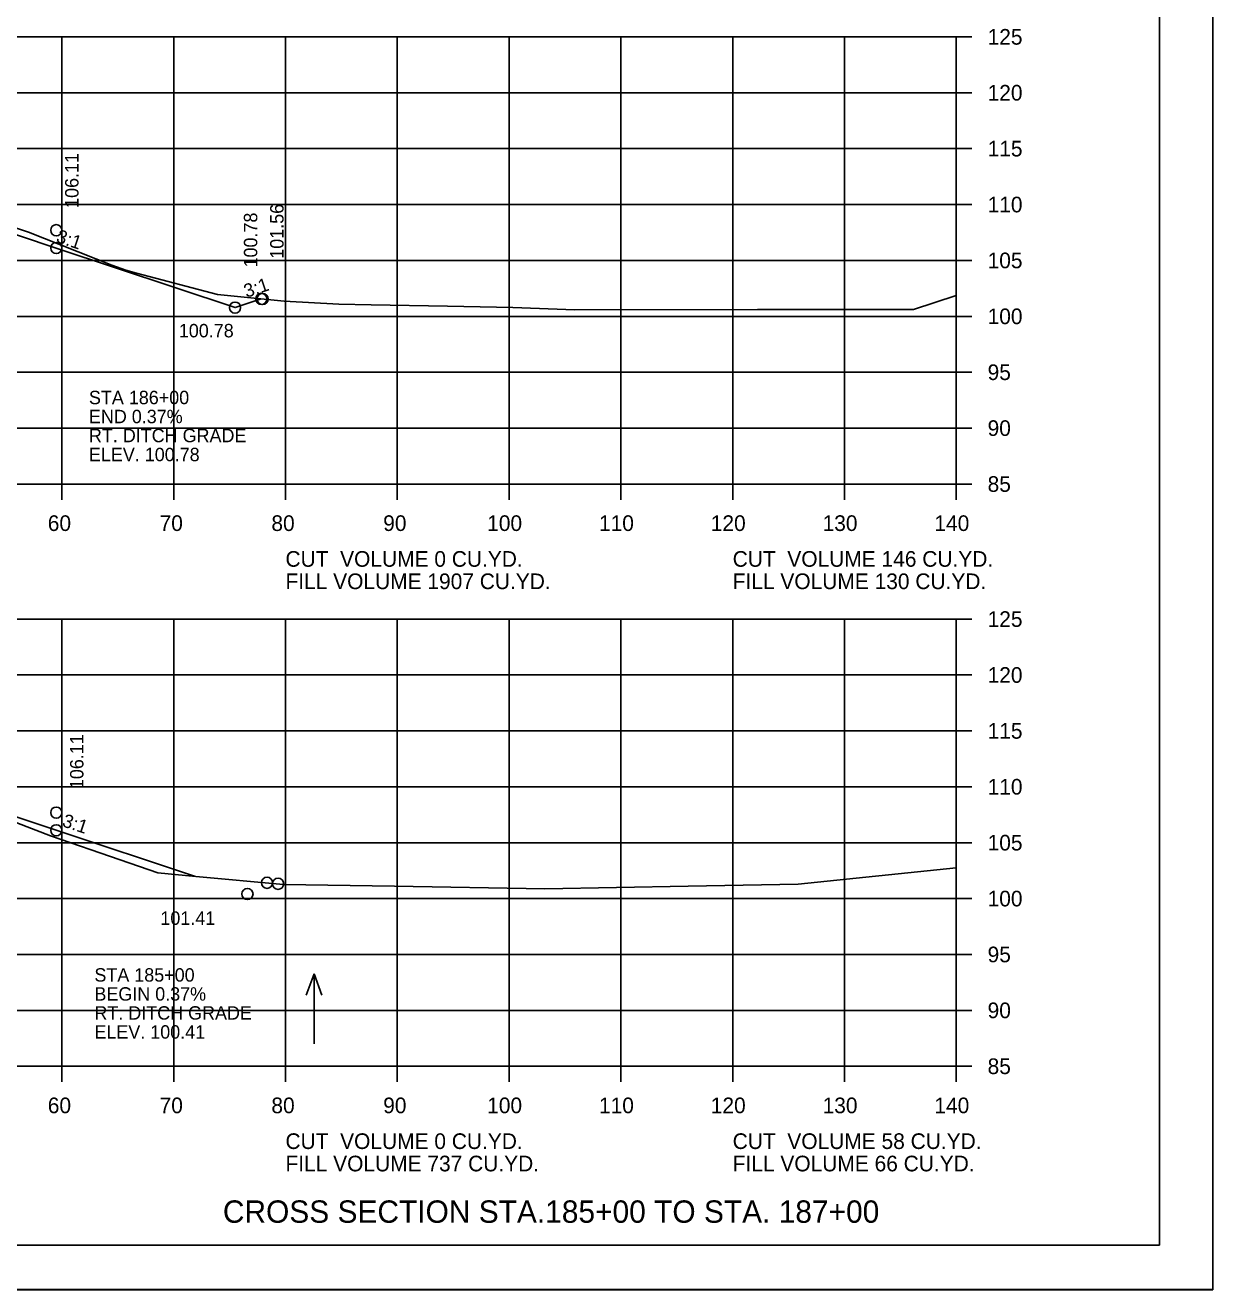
# Model space of a CAD drawing. Extents: x 1175611 to 1176402, y -433344 to -416213.
# Drawn here: x 1175837.7 to 1175943.9, y -426516.7 to -426403.6 of the extents above; entities that cross this region are included whole.
import ezdxf

# ---------------------------------------------------------------- set-up
doc = ezdxf.new("R2010")
doc.units = 0
for name, color, linetype in [('Default', 7, 'Continuous'), ('R_Axis', 7, 'Continuous'), ('R_Axis Annot', 7, 'Continuous'), ('R_Border', 7, 'Continuous'), ('R_Draft', 7, 'Continuous'), ('R_Exist Surface', 7, 'Continuous'), ('R_Fin Surface', 7, 'Continuous'), ('R_Grid', 7, 'Continuous'), ('R_No Plot', 7, 'Continuous'), ('R_Water Annot', 7, 'Continuous'), ('R_Xsect Elev', 7, 'Continuous'), ('R_Xsect Slope', 7, 'Continuous')]:
    doc.layers.add(name, color=color, linetype=linetype)

msp = doc.modelspace()

# ---------------------------------------------------------------- linework, layer by layer
at = {"layer": 'R_Axis'}
for p, q in [((1175920.97, -426444.65), (1175920.97, -426404.65)), ((1175922.37, -426404.65), (1175920.97, -426404.65)), ((1175922.37, -426409.65), (1175920.97, -426409.65)), ((1175922.37, -426414.65), (1175920.97, -426414.65)), ((1175922.37, -426419.65), (1175920.97, -426419.65)), ((1175922.37, -426424.65), (1175920.97, -426424.65)), ((1175922.37, -426429.65), (1175920.97, -426429.65)), ((1175922.37, -426434.65), (1175920.97, -426434.65)), ((1175922.37, -426439.65), (1175920.97, -426439.65)), ((1175640.97, -426444.65), (1175920.97, -426444.65)), ((1175840.97, -426446.05), (1175840.97, -426444.65)), ((1175850.97, -426446.05), (1175850.97, -426444.65)), ((1175860.97, -426446.05), (1175860.97, -426444.65)), ((1175870.97, -426446.05), (1175870.97, -426444.65)), ((1175880.97, -426446.05), (1175880.97, -426444.65)), ((1175890.97, -426446.05), (1175890.97, -426444.65)), ((1175900.97, -426446.05), (1175900.97, -426444.65)), ((1175910.97, -426446.05), (1175910.97, -426444.65)), ((1175920.97, -426446.05), (1175920.97, -426444.65)), ((1175922.37, -426444.65), (1175920.97, -426444.65)), ((1175920.97, -426496.73), (1175920.97, -426456.73)), ((1175922.37, -426456.73), (1175920.97, -426456.73)), ((1175922.37, -426461.73), (1175920.97, -426461.73)), ((1175922.37, -426466.73), (1175920.97, -426466.73)), ((1175922.37, -426471.73), (1175920.97, -426471.73)), ((1175922.37, -426476.73), (1175920.97, -426476.73)), ((1175922.37, -426481.73), (1175920.97, -426481.73)), ((1175922.37, -426486.73), (1175920.97, -426486.73)), ((1175922.37, -426491.73), (1175920.97, -426491.73)), ((1175640.97, -426496.73), (1175920.97, -426496.73)), ((1175840.97, -426498.13), (1175840.97, -426496.73)), ((1175850.97, -426498.13), (1175850.97, -426496.73)), ((1175860.97, -426498.13), (1175860.97, -426496.73)), ((1175870.97, -426498.13), (1175870.97, -426496.73)), ((1175880.97, -426498.13), (1175880.97, -426496.73)), ((1175890.97, -426498.13), (1175890.97, -426496.73)), ((1175900.97, -426498.13), (1175900.97, -426496.73)), ((1175910.97, -426498.13), (1175910.97, -426496.73)), ((1175920.97, -426498.13), (1175920.97, -426496.73)), ((1175922.37, -426496.73), (1175920.97, -426496.73))]:
    msp.add_line(p, q, dxfattribs=at)
at = {"layer": 'R_Border'}
for q in [(1175939.15, -426307.27), (1175622.97, -426512.73)]:
    msp.add_line((1175939.15, -426512.73), q, dxfattribs=at)
at = {"layer": 'R_Exist Surface'}
for points in [[(1175833.72, -426420.68), (1175837.99, -426422.12), (1175845.43, -426425.07), (1175846.69, -426425.52), (1175847.63, -426425.78), (1175854.88, -426427.71), (1175860.86, -426428.28), (1175865.73, -426428.57), (1175868.62, -426428.63), (1175875.45, -426428.73), (1175881.31, -426428.87), (1175886.84, -426429.07), (1175903.2, -426429.04), (1175917.14, -426429.03), (1175920.97, -426427.8)], [(1175833.52, -426473.65), (1175839.95, -426476.12), (1175846.17, -426478.28), (1175849.56, -426479.44), (1175852.94, -426479.75), (1175860.8, -426480.46), (1175870.71, -426480.63), (1175884.17, -426480.87), (1175896.99, -426480.62), (1175906.82, -426480.43), (1175920.97, -426478.97)]]:
    msp.add_lwpolyline(points, dxfattribs=at)
at = {"layer": 'R_Fin Surface'}
for points in [[(1175704.22, -426429.29), (1175721.47, -426423.54), (1175734.45, -426419.21), (1175737.97, -426418.04), (1175749.47, -426417.58), (1175751.47, -426417.54), (1175780.97, -426416.95), (1175810.47, -426417.54), (1175812.47, -426417.58), (1175823.97, -426418.04), (1175827.49, -426419.21), (1175840.47, -426423.54), (1175856.46, -426428.87), (1175858.81, -426428.09)], [(1175705.54, -426480.93), (1175721.47, -426475.62), (1175734.45, -426471.3), (1175737.97, -426470.12), (1175749.47, -426469.66), (1175751.47, -426469.62), (1175780.97, -426469.03), (1175810.47, -426469.62), (1175812.47, -426469.66), (1175823.97, -426470.12), (1175827.49, -426471.3), (1175840.47, -426475.62), (1175852.83, -426479.74)]]:
    msp.add_lwpolyline(points, dxfattribs=at)
at = {"layer": 'R_Grid'}
for p, q in [((1175640.97, -426404.65), (1175920.97, -426404.65)), ((1175840.97, -426444.65), (1175840.97, -426404.65)), ((1175850.97, -426444.65), (1175850.97, -426404.65)), ((1175860.97, -426444.65), (1175860.97, -426404.65)), ((1175870.97, -426444.65), (1175870.97, -426404.65)), ((1175880.97, -426444.65), (1175880.97, -426404.65)), ((1175890.97, -426444.65), (1175890.97, -426404.65)), ((1175900.97, -426444.65), (1175900.97, -426404.65)), ((1175910.97, -426444.65), (1175910.97, -426404.65)), ((1175920.97, -426444.65), (1175920.97, -426404.65)), ((1175640.97, -426409.65), (1175920.97, -426409.65)), ((1175640.97, -426414.65), (1175920.97, -426414.65)), ((1175640.97, -426419.65), (1175920.97, -426419.65)), ((1175640.97, -426424.65), (1175920.97, -426424.65)), ((1175640.97, -426429.65), (1175920.97, -426429.65)), ((1175640.97, -426434.65), (1175920.97, -426434.65)), ((1175640.97, -426439.65), (1175920.97, -426439.65)), ((1175640.97, -426444.65), (1175920.97, -426444.65)), ((1175640.97, -426456.73), (1175920.97, -426456.73)), ((1175840.97, -426496.73), (1175840.97, -426456.73)), ((1175850.97, -426496.73), (1175850.97, -426456.73)), ((1175860.97, -426496.73), (1175860.97, -426456.73)), ((1175870.97, -426496.73), (1175870.97, -426456.73)), ((1175880.97, -426496.73), (1175880.97, -426456.73)), ((1175890.97, -426496.73), (1175890.97, -426456.73)), ((1175900.97, -426496.73), (1175900.97, -426456.73)), ((1175910.97, -426496.73), (1175910.97, -426456.73)), ((1175920.97, -426496.73), (1175920.97, -426456.73)), ((1175640.97, -426461.73), (1175920.97, -426461.73)), ((1175640.97, -426466.73), (1175920.97, -426466.73)), ((1175640.97, -426471.73), (1175920.97, -426471.73)), ((1175640.97, -426476.73), (1175920.97, -426476.73)), ((1175640.97, -426481.73), (1175920.97, -426481.73)), ((1175640.97, -426486.73), (1175920.97, -426486.73)), ((1175640.97, -426491.73), (1175920.97, -426491.73)), ((1175640.97, -426496.73), (1175920.97, -426496.73))]:
    msp.add_line(p, q, dxfattribs=at)
at = {"layer": 'R_No Plot'}
msp.add_line((1175610.57, -426516.71), (1175943.91, -426516.71), dxfattribs=at)
msp.add_lwpolyline([(1175610.57, -426303.38), (1175943.91, -426303.38), (1175943.91, -426516.72), (1175610.57, -426516.72)], close=True, dxfattribs=at)
for centre in [(1175840.47, -426421.95), (1175840.47, -426423.54), (1175858.81, -426428.09), (1175858.81, -426428.09), (1175858.92, -426428.1), (1175858.92, -426428.1), (1175856.46, -426428.87), (1175856.46, -426428.87), (1175840.47, -426474.04), (1175840.47, -426475.62), (1175857.57, -426481.32), (1175857.57, -426481.32), (1175859.32, -426480.32), (1175860.31, -426480.41), (1175860.31, -426480.41)]:
    msp.add_circle(centre, 0.5, dxfattribs=at)
at = {"layer": 'R_Water Annot'}
for p, q in [((1175863.53, -426488.45), (1175862.83, -426490.37)), ((1175863.53, -426494.73), (1175863.53, -426488.45)), ((1175863.53, -426488.45), (1175864.23, -426490.37))]:
    msp.add_line(p, q, dxfattribs=at)

# ---------------------------------------------------------------- texts
at = {"layer": 'Default'}
for s, p in [('CUT  VOLUME 0 CU.YD.', (1175860.97, -426452.05)), ('CUT  VOLUME 146 CU.YD.', (1175900.97, -426452.05)), ('FILL VOLUME 1907 CU.YD.', (1175860.97, -426454.05)), ('FILL VOLUME 130 CU.YD.', (1175900.97, -426454.05)), ('CUT  VOLUME 0 CU.YD.', (1175860.97, -426504.13)), ('CUT  VOLUME 58 CU.YD.', (1175900.97, -426504.13)), ('FILL VOLUME 737 CU.YD.', (1175860.97, -426506.13)), ('FILL VOLUME 66 CU.YD.', (1175900.97, -426506.13))]:
    msp.add_text(s, height=1.4, dxfattribs=at).set_placement(p)
at = {"layer": 'R_Axis Annot'}
for s, p in [('125', (1175923.77, -426405.35)), ('120', (1175923.77, -426410.35)), ('115', (1175923.77, -426415.35)), ('110', (1175923.77, -426420.35)), ('105', (1175923.77, -426425.35)), ('100', (1175923.77, -426430.35)), ('95', (1175923.77, -426435.35)), ('90', (1175923.77, -426440.35)), ('85', (1175923.77, -426445.35)), ('60', (1175839.71, -426448.85)), ('70', (1175849.71, -426448.85)), ('80', (1175859.71, -426448.85)), ('90', (1175869.71, -426448.85)), ('100', (1175879.01, -426448.85)), ('110', (1175889.01, -426448.85)), ('120', (1175899.01, -426448.85)), ('130', (1175909.01, -426448.85)), ('140', (1175919.01, -426448.85)), ('125', (1175923.77, -426457.43)), ('120', (1175923.77, -426462.43)), ('115', (1175923.77, -426467.43)), ('110', (1175923.77, -426472.43)), ('105', (1175923.77, -426477.43)), ('100', (1175923.77, -426482.43)), ('95', (1175923.77, -426487.43)), ('90', (1175923.77, -426492.43)), ('85', (1175923.77, -426497.43)), ('60', (1175839.71, -426500.93)), ('70', (1175849.71, -426500.93)), ('80', (1175859.71, -426500.93)), ('90', (1175869.71, -426500.93)), ('100', (1175879.01, -426500.93)), ('110', (1175889.01, -426500.93)), ('120', (1175899.01, -426500.93)), ('130', (1175909.01, -426500.93)), ('140', (1175919.01, -426500.93))]:
    msp.add_text(s, height=1.4, dxfattribs=at).set_placement(p)
at = {"layer": 'R_Draft'}
msp.add_text('CROSS SECTION STA.185+00 TO STA. 187+00', height=2, dxfattribs=at).set_placement((1175855.37, -426510.73))
at = {"layer": 'R_Water Annot'}
for s, p in [('STA 186+00', (1175843.39, -426437.51)), ('END 0.37%', (1175843.39, -426439.21)), ('RT. DITCH GRADE', (1175843.39, -426440.91)), ('ELEV. 100.78', (1175843.39, -426442.61)), ('STA 185+00', (1175843.88, -426489.16)), ('BEGIN 0.37%', (1175843.88, -426490.86)), ('RT. DITCH GRADE', (1175843.88, -426492.56)), ('ELEV. 100.41', (1175843.88, -426494.26))]:
    msp.add_text(s, height=1.2, dxfattribs=at).set_placement(p)
at = {"layer": 'R_Xsect Elev'}
for s, p in [('106.11', (1175842.46, -426419.95)), ('101.56', (1175860.8, -426424.5)), ('100.78', (1175858.45, -426425.28)), ('106.11', (1175842.9, -426471.94))]:
    msp.add_text(s, height=1.2, rotation=90, dxfattribs=at).set_placement(p)
for s, p in [('100.78', (1175851.43, -426431.53)), ('101.41', (1175849.78, -426484.08))]:
    msp.add_text(s, height=1.2, dxfattribs=at).set_placement(p)
at = {"layer": 'R_Xsect Slope'}
for rotation, p in [(341.5651, (1175840.38, -426422.98)), (18.4349, (1175857.48, -426428)), (341.5651, (1175840.93, -426475.25))]:
    msp.add_text('3:1', height=1.2, rotation=rotation, dxfattribs=at).set_placement(p)

doc.saveas('drawing.dxf')
